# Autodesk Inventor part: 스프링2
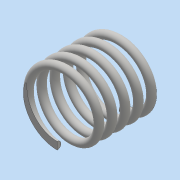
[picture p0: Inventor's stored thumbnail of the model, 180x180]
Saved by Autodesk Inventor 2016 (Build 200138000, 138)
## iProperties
Created: 2019-11
Part Number: 스프링2
Material: 일반
Document SubType Name: Modeling
Designer: user
Density: 1 g/cm^3
Appearance: 기본값
Mass: 0.818768 g
Surface Area: 16.6978 cm^2
Volume: 0.818768 cm^3
Author: user
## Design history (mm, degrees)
sketch "스케치1"
  geometry: L1 (0, 0)-(17.5, 0); L2 (17.5, 0)-(17.5, -8.5); L3 (17.5, -8.5)-(0, -8.5); L4 (0, -8.5)-(0, 0); C1 r 1 at (0, -8.5)
  constraints: 8 end point, 2 parallel, 1 centre point, 1 coincident, 1 horizontal, 1 perpendicular
  dimensions: "d0" = 17.5 distance of L1.start L1.end (derived); "d1" = 17 diameter of L3 L1; "d2" = 2 diameter of C1
feature "코일1" sketch "스케치1" pitch "d3" = 10; turns "d5" = 5; dims "d4" = 17.5 (= d0), "d6" = 0, angle "d7" = 90 deg, angle "d8" = 90 deg, "d9" = 0, "d10" = 0
sketch "스케치2"
  geometry: L1 (-15.996, 0)-(15.996, 0); L2 (15.996, 0)-(15.996, 17.5); L3 (15.996, 17.5)-(-15.996, 17.5); L4 (-15.996, 17.5)-(-15.996, 0); 2 further points
  constraints: 8 end point, 2 parallel, 1 coincident, 1 horizontal, 1 midpoint, 1 perpendicular
  dimensions: "d12" = 31.99189 distance between parallel lines of L2 L4; "d13" = 17.5 distance of L1.end L2.end (= d0)
extrude "돌출1" sketch "스케치2" stored distance "d14" = 38.25; taper "d15" = 0 deg
node "솔리드1"
